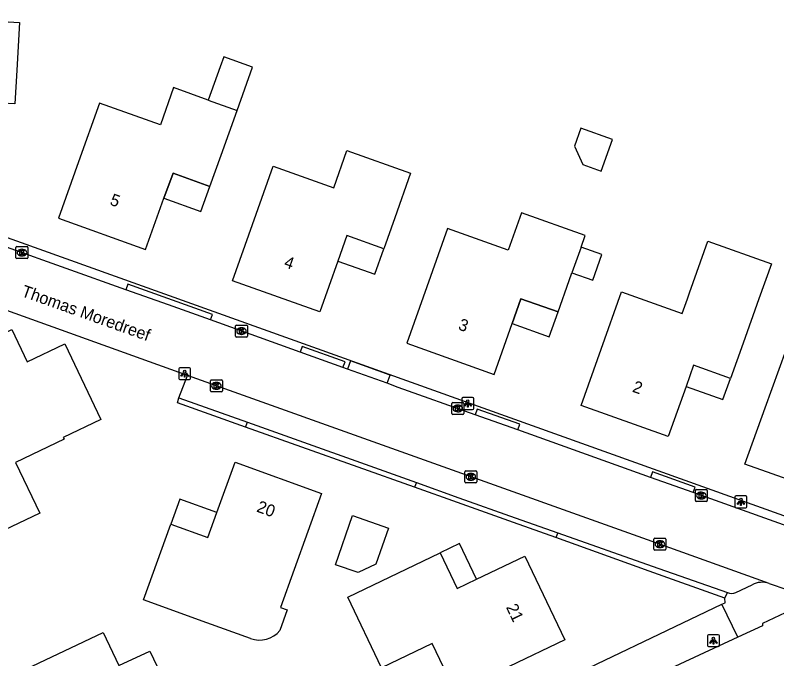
# Model space of a CAD drawing. Extents: x 163268 to 164360, y 381529 to 382285.
# Drawn here: x 163633.8 to 163697.5, y 381632.5 to 381686.4 of the extents above; entities that cross this region are included whole.
import ezdxf

# ---------------------------------------------------------------- set-up
doc = ezdxf.new("R2010")
doc.units = 0
for name, color, linetype in [('IMGEO_Fietspad_gesloten', 7, 'Continuous'), ('IMGEO_Groenvoorziening', 7, 'Continuous'), ('IMGEO_Kolk', 7, 'Continuous'), ('IMGEO_Lichtpunt', 7, 'Continuous'), ('IMGEO_Openbare_ruimte_label', 7, 'Continuous'), ('IMGEO_Pand', 7, 'Continuous'), ('IMGEO_Pand_nummerreeks', 7, 'Continuous'), ('IMGEO_Pand_overbouw', 7, 'Continuous'), ('IMGEO_Parkeervlak_open', 7, 'Continuous'), ('IMGEO_Rijbaan_lokaal_open', 7, 'Continuous'), ('IMGEO_Voetpad_open', 7, 'Continuous')]:
    doc.layers.add(name, color=color, linetype=linetype)

msp = doc.modelspace()

# ---------------------------------------------------------------- linework, layer by layer
at = {"layer": 'IMGEO_Fietspad_gesloten'}
for points in [[(163698.247, 381636.386), (163696.339, 381635.498), (163696.333, 381635.308), (163694.284, 381634.354)], [(163694.284, 381634.354), (163682.934, 381629.066), (163588.96, 381585.345)]]:
    msp.add_lwpolyline(points, dxfattribs=at)
at = {"layer": 'IMGEO_Groenvoorziening'}
for points in [[(163692.948, 381637.102), (163693.217, 381637.23), (163693.201, 381637.598)], [(163623.496, 381604.168), (163677.889, 381629.916), (163692.948, 381637.102)], [(163694.284, 381634.354), (163692.948, 381637.102)]]:
    msp.add_lwpolyline(points, dxfattribs=at)
at = {"layer": 'IMGEO_Kolk'}
for p, q in [((163633.827, 381666.099), (163633.827, 381666.951)), ((163633.902, 381667.025), (163634.754, 381667.025)), ((163634.828, 381666.951), (163634.828, 381666.099)), ((163634.315, 381666.805), (163634.34, 381666.805)), ((163634.754, 381666.025), (163633.902, 381666.025)), ((163634.338, 381666.245), (163634.313, 381666.245)), ((163652.211, 381659.532), (163652.211, 381660.384)), ((163652.286, 381660.458), (163653.138, 381660.458)), ((163652.699, 381660.238), (163652.724, 381660.238)), ((163653.212, 381660.384), (163653.212, 381659.532)), ((163653.138, 381659.458), (163652.286, 381659.458)), ((163652.722, 381659.678), (163652.697, 381659.678)), ((163650.11, 381654.948), (163650.11, 381655.8)), ((163650.185, 381655.874), (163651.037, 381655.874)), ((163650.598, 381655.654), (163650.623, 381655.654)), ((163651.111, 381655.8), (163651.111, 381654.948)), ((163651.037, 381654.874), (163650.185, 381654.874)), ((163650.621, 381655.094), (163650.596, 381655.094)), ((163670.325, 381653.059), (163670.325, 381653.911)), ((163670.4, 381653.985), (163671.252, 381653.985)), ((163670.813, 381653.765), (163670.838, 381653.765)), ((163671.326, 381653.911), (163671.326, 381653.059)), ((163671.252, 381652.985), (163670.4, 381652.985)), ((163670.836, 381653.205), (163670.811, 381653.205)), ((163671.421, 381647.336), (163671.421, 381648.188)), ((163671.496, 381648.262), (163672.348, 381648.262)), ((163671.909, 381648.042), (163671.934, 381648.042)), ((163672.422, 381648.188), (163672.422, 381647.336)), ((163672.348, 381647.262), (163671.496, 381647.262)), ((163671.932, 381647.482), (163671.907, 381647.482)), ((163690.722, 381645.769), (163690.722, 381646.621)), ((163690.797, 381646.695), (163691.649, 381646.695)), ((163691.723, 381646.621), (163691.723, 381645.769)), ((163691.233, 381645.915), (163691.208, 381645.915)), ((163691.21, 381646.475), (163691.235, 381646.475)), ((163691.649, 381645.695), (163690.797, 381645.695)), ((163687.255, 381641.699), (163687.255, 381642.551)), ((163687.33, 381642.625), (163688.182, 381642.625)), ((163687.743, 381642.405), (163687.768, 381642.405)), ((163688.256, 381642.551), (163688.256, 381641.699)), ((163688.182, 381641.625), (163687.33, 381641.625)), ((163687.766, 381641.845), (163687.741, 381641.845))]:
    msp.add_line(p, q, dxfattribs=at)
for points in [[(163633.827, 381666.099), (163633.827, 381666.951)], [(163633.902, 381667.025), (163634.754, 381667.025)], [(163634.828, 381666.951), (163634.828, 381666.099)], [(163634.148, 381666.725), (163634.271, 381666.725), (163634.271, 381666.574), (163634.401, 381666.725), (163634.565, 381666.725), (163634.419, 381666.574), (163634.572, 381666.325), (163634.42, 381666.325), (163634.335, 381666.489), (163634.271, 381666.422), (163634.271, 381666.325), (163634.148, 381666.325), (163634.148, 381666.725)], [(163634.754, 381666.025), (163633.902, 381666.025)], [(163652.211, 381659.532), (163652.211, 381660.384)], [(163652.286, 381660.458), (163653.138, 381660.458)], [(163652.532, 381660.158), (163652.655, 381660.158), (163652.655, 381660.007), (163652.785, 381660.158), (163652.949, 381660.158), (163652.803, 381660.007), (163652.956, 381659.758), (163652.804, 381659.758), (163652.719, 381659.922), (163652.655, 381659.855), (163652.655, 381659.758), (163652.532, 381659.758), (163652.532, 381660.158)], [(163653.212, 381660.384), (163653.212, 381659.532)], [(163653.138, 381659.458), (163652.286, 381659.458)], [(163650.11, 381654.948), (163650.11, 381655.8)], [(163650.185, 381655.874), (163651.037, 381655.874)], [(163650.431, 381655.574), (163650.554, 381655.574), (163650.554, 381655.423), (163650.684, 381655.574), (163650.848, 381655.574), (163650.702, 381655.423), (163650.855, 381655.174), (163650.703, 381655.174), (163650.618, 381655.338), (163650.554, 381655.271), (163650.554, 381655.174), (163650.431, 381655.174), (163650.431, 381655.574)], [(163651.111, 381655.8), (163651.111, 381654.948)], [(163651.037, 381654.874), (163650.185, 381654.874)], [(163670.325, 381653.059), (163670.325, 381653.911)], [(163670.4, 381653.985), (163671.252, 381653.985)], [(163670.646, 381653.685), (163670.769, 381653.685), (163670.769, 381653.534), (163670.899, 381653.685), (163671.063, 381653.685), (163670.917, 381653.534), (163671.07, 381653.285), (163670.918, 381653.285), (163670.833, 381653.449), (163670.769, 381653.382), (163670.769, 381653.285), (163670.646, 381653.285), (163670.646, 381653.685)], [(163671.326, 381653.911), (163671.326, 381653.059)], [(163671.252, 381652.985), (163670.4, 381652.985)], [(163671.421, 381647.336), (163671.421, 381648.188)], [(163671.496, 381648.262), (163672.348, 381648.262)], [(163671.742, 381647.962), (163671.865, 381647.962), (163671.865, 381647.811), (163671.995, 381647.962), (163672.159, 381647.962), (163672.013, 381647.811), (163672.166, 381647.562), (163672.014, 381647.562), (163671.929, 381647.726), (163671.865, 381647.659), (163671.865, 381647.562), (163671.742, 381647.562), (163671.742, 381647.962)], [(163672.422, 381648.188), (163672.422, 381647.336)], [(163672.348, 381647.262), (163671.496, 381647.262)], [(163690.722, 381645.769), (163690.722, 381646.621)], [(163690.797, 381646.695), (163691.649, 381646.695)], [(163691.723, 381646.621), (163691.723, 381645.769)], [(163691.043, 381646.395), (163691.166, 381646.395), (163691.166, 381646.244), (163691.296, 381646.395), (163691.46, 381646.395), (163691.314, 381646.244), (163691.467, 381645.995), (163691.315, 381645.995), (163691.23, 381646.159), (163691.166, 381646.092), (163691.166, 381645.995), (163691.043, 381645.995), (163691.043, 381646.395)], [(163691.649, 381645.695), (163690.797, 381645.695)], [(163687.255, 381641.699), (163687.255, 381642.551)], [(163687.33, 381642.625), (163688.182, 381642.625)], [(163687.576, 381642.325), (163687.699, 381642.325), (163687.699, 381642.174), (163687.829, 381642.325), (163687.993, 381642.325), (163687.847, 381642.174), (163688, 381641.925), (163687.848, 381641.925), (163687.763, 381642.089), (163687.699, 381642.022), (163687.699, 381641.925), (163687.576, 381641.925), (163687.576, 381642.325)], [(163688.256, 381642.551), (163688.256, 381641.699)], [(163688.182, 381641.625), (163687.33, 381641.625)]]:
    msp.add_lwpolyline(points, dxfattribs=at)
for centre, start, end in [((163633.904, 381666.949), 91.55205, 178.44795), ((163633.904, 381666.949), 91.55205, 178.44795), ((163634.752, 381666.949), 1.55205, 88.44795), ((163634.752, 381666.949), 1.55205, 88.44795), ((163633.904, 381666.101), 181.55205, 268.44795), ((163633.904, 381666.101), 181.55205, 268.44795), ((163634.752, 381666.101), 271.55205, 358.44795), ((163634.752, 381666.101), 271.55205, 358.44795), ((163652.288, 381660.382), 91.55205, 178.44795), ((163652.288, 381660.382), 91.55205, 178.44795), ((163653.136, 381660.382), 1.55205, 88.44795), ((163653.136, 381660.382), 1.55205, 88.44795), ((163652.288, 381659.534), 181.55205, 268.44795), ((163652.288, 381659.534), 181.55205, 268.44795), ((163653.136, 381659.534), 271.55205, 358.44795), ((163653.136, 381659.534), 271.55205, 358.44795), ((163650.187, 381655.798), 91.55205, 178.44795), ((163650.187, 381655.798), 91.55205, 178.44795), ((163651.035, 381655.798), 1.55205, 88.44795), ((163651.035, 381655.798), 1.55205, 88.44795), ((163650.187, 381654.95), 181.55205, 268.44795), ((163650.187, 381654.95), 181.55205, 268.44795), ((163651.035, 381654.95), 271.55205, 358.44795), ((163651.035, 381654.95), 271.55205, 358.44795), ((163670.402, 381653.909), 91.55205, 178.44795), ((163670.402, 381653.909), 91.55205, 178.44795), ((163671.25, 381653.909), 1.55205, 88.44795), ((163671.25, 381653.909), 1.55205, 88.44795), ((163670.402, 381653.061), 181.55205, 268.44795), ((163670.402, 381653.061), 181.55205, 268.44795), ((163671.25, 381653.061), 271.55205, 358.44795), ((163671.25, 381653.061), 271.55205, 358.44795), ((163671.498, 381648.186), 91.55205, 178.44795), ((163671.498, 381648.186), 91.55205, 178.44795), ((163672.346, 381648.186), 1.55205, 88.44795), ((163672.346, 381648.186), 1.55205, 88.44795), ((163671.498, 381647.338), 181.55205, 268.44795), ((163671.498, 381647.338), 181.55205, 268.44795), ((163672.346, 381647.338), 271.55205, 358.44795), ((163672.346, 381647.338), 271.55205, 358.44795), ((163690.799, 381646.619), 91.55205, 178.44795), ((163690.799, 381646.619), 91.55205, 178.44795), ((163691.647, 381646.619), 1.55205, 88.44795), ((163691.647, 381646.619), 1.55205, 88.44795), ((163690.799, 381645.771), 181.55205, 268.44795), ((163690.799, 381645.771), 181.55205, 268.44795), ((163691.647, 381645.771), 271.55205, 358.44795), ((163691.647, 381645.771), 271.55205, 358.44795), ((163687.332, 381642.549), 91.55205, 178.44795), ((163687.332, 381642.549), 91.55205, 178.44795), ((163688.18, 381642.549), 1.55205, 88.44795), ((163688.18, 381642.549), 1.55205, 88.44795), ((163687.332, 381641.701), 181.55205, 268.44795), ((163687.332, 381641.701), 181.55205, 268.44795), ((163688.18, 381641.701), 271.55205, 358.44795), ((163688.18, 381641.701), 271.55205, 358.44795)]:
    msp.add_arc(centre, 0.0765, start, end, dxfattribs=at)
for centre, major_axis, ratio, start_param, end_param in [((163634.314, 381666.525), (-0.387, 0.002), 0.722429, 4.712389, 7.853982), ((163634.339, 381666.525), (-0.39, 0.002), 0.717154, 1.570796, 4.712389), ((163652.698, 381659.958), (-0.387, 0.002), 0.722429, 4.712389, 7.853982), ((163652.723, 381659.958), (-0.39, 0.002), 0.717154, 1.570796, 4.712389), ((163650.597, 381655.374), (-0.387, 0.002), 0.722429, 4.712389, 7.853982), ((163650.622, 381655.374), (-0.39, 0.002), 0.717154, 1.570796, 4.712389), ((163670.812, 381653.485), (-0.387, 0.002), 0.722429, 4.712389, 7.853982), ((163670.837, 381653.485), (-0.39, 0.002), 0.717154, 1.570796, 4.712389), ((163671.908, 381647.762), (-0.387, 0.002), 0.722429, 4.712389, 7.853982), ((163671.933, 381647.762), (-0.39, 0.002), 0.717154, 1.570796, 4.712389), ((163691.209, 381646.195), (-0.387, 0.002), 0.722429, 4.712389, 7.853982), ((163691.234, 381646.195), (-0.39, 0.002), 0.717154, 1.570796, 4.712389), ((163687.742, 381642.125), (-0.387, 0.002), 0.722429, 4.712389, 7.853982), ((163687.767, 381642.125), (-0.39, 0.002), 0.717154, 1.570796, 4.712389)]:
    msp.add_ellipse(centre, major_axis=major_axis, ratio=ratio, start_param=start_param, end_param=end_param, dxfattribs=at)
at = {"layer": 'IMGEO_Lichtpunt'}
for p, q in [((163647.455, 381656.797), (163647.455, 381655.99)), ((163647.455, 381656.797), (163647.455, 381655.99)), ((163648.357, 381656.892), (163647.549, 381656.892)), ((163648.357, 381656.892), (163647.549, 381656.892)), ((163648.451, 381655.99), (163648.451, 381656.797)), ((163648.451, 381655.99), (163648.451, 381656.797)), ((163647.549, 381655.896), (163648.357, 381655.896)), ((163647.549, 381655.896), (163648.357, 381655.896)), ((163671.162, 381654.297), (163671.162, 381653.49)), ((163671.162, 381654.297), (163671.162, 381653.49)), ((163672.064, 381654.392), (163671.256, 381654.392)), ((163672.064, 381654.392), (163671.256, 381654.392)), ((163672.158, 381653.49), (163672.158, 381654.297)), ((163672.158, 381653.49), (163672.158, 381654.297)), ((163671.256, 381653.396), (163672.064, 381653.396)), ((163671.256, 381653.396), (163672.064, 381653.396)), ((163694.039, 381646.073), (163694.039, 381645.266)), ((163694.039, 381646.073), (163694.039, 381645.266)), ((163694.941, 381646.168), (163694.133, 381646.168)), ((163694.941, 381646.168), (163694.133, 381646.168)), ((163695.035, 381645.266), (163695.035, 381646.073)), ((163695.035, 381645.266), (163695.035, 381646.073)), ((163694.133, 381645.172), (163694.941, 381645.172)), ((163694.133, 381645.172), (163694.941, 381645.172)), ((163691.738, 381634.455), (163691.738, 381633.648)), ((163691.738, 381634.455), (163691.738, 381633.648)), ((163692.64, 381634.55), (163691.832, 381634.55)), ((163692.64, 381634.55), (163691.832, 381634.55)), ((163692.734, 381633.648), (163692.734, 381634.455)), ((163692.734, 381633.648), (163692.734, 381634.455)), ((163691.832, 381633.554), (163692.64, 381633.554)), ((163691.832, 381633.554), (163692.64, 381633.554))]:
    msp.add_line(p, q, dxfattribs=at)
for points in [[(163647.829, 381656.461), (163647.868, 381656.433), (163647.68, 381656.171), (163647.642, 381656.198), (163647.829, 381656.461)], [(163647.931, 381656.413), (163647.978, 381656.413), (163647.978, 381656.091), (163647.931, 381656.091), (163647.931, 381656.413)], [(163648.041, 381656.433), (163648.079, 381656.46), (163648.266, 381656.198), (163648.227, 381656.17), (163648.041, 381656.433)], [(163671.536, 381653.961), (163671.575, 381653.933), (163671.387, 381653.671), (163671.349, 381653.698), (163671.536, 381653.961)], [(163671.638, 381653.913), (163671.685, 381653.913), (163671.685, 381653.591), (163671.638, 381653.591), (163671.638, 381653.913)], [(163671.748, 381653.933), (163671.786, 381653.96), (163671.973, 381653.698), (163671.934, 381653.67), (163671.748, 381653.933)], [(163694.413, 381645.737), (163694.452, 381645.709), (163694.264, 381645.447), (163694.226, 381645.474), (163694.413, 381645.737)], [(163694.515, 381645.689), (163694.562, 381645.689), (163694.562, 381645.367), (163694.515, 381645.367), (163694.515, 381645.689)], [(163694.625, 381645.709), (163694.663, 381645.736), (163694.85, 381645.474), (163694.811, 381645.446), (163694.625, 381645.709)], [(163692.112, 381634.119), (163692.151, 381634.091), (163691.963, 381633.829), (163691.925, 381633.856), (163692.112, 381634.119)], [(163692.214, 381634.071), (163692.261, 381634.071), (163692.261, 381633.749), (163692.214, 381633.749), (163692.214, 381634.071)], [(163692.324, 381634.091), (163692.362, 381634.118), (163692.549, 381633.856), (163692.51, 381633.828), (163692.324, 381634.091)]]:
    msp.add_lwpolyline(points, dxfattribs=at)
for centre in [(163647.954, 381656.595), (163671.661, 381654.095), (163694.538, 381645.871), (163692.237, 381634.253)]:
    msp.add_circle(centre, 0.0994, dxfattribs=at)
for centre, start, end in [((163647.549, 381656.797), 90, 180), ((163647.549, 381656.797), 90, 180), ((163648.357, 381656.797), 0, 90), ((163648.357, 381656.797), 0, 90), ((163647.549, 381655.99), 180, 270), ((163647.549, 381655.99), 180, 270), ((163648.357, 381655.99), 270, 0), ((163648.357, 381655.99), 270, 360), ((163671.256, 381654.297), 90, 180), ((163671.256, 381654.297), 90, 180), ((163672.064, 381654.297), 0, 90), ((163672.064, 381654.297), 0, 90), ((163671.256, 381653.49), 180, 270), ((163671.256, 381653.49), 180, 270), ((163672.064, 381653.49), 270, 0), ((163672.064, 381653.49), 270, 360), ((163694.133, 381646.073), 90, 180), ((163694.133, 381646.073), 90, 180), ((163694.941, 381646.073), 0, 90), ((163694.941, 381646.073), 0, 90), ((163694.133, 381645.266), 180, 270), ((163694.133, 381645.266), 180, 270), ((163694.941, 381645.266), 270, 0), ((163694.941, 381645.266), 270, 360), ((163691.832, 381634.455), 90, 180), ((163691.832, 381634.455), 90, 180), ((163692.64, 381634.455), 0, 90), ((163692.64, 381634.455), 0, 90), ((163691.832, 381633.648), 180, 270), ((163691.832, 381633.648), 180, 270), ((163692.64, 381633.648), 270, 0), ((163692.64, 381633.648), 270, 360)]:
    msp.add_arc(centre, 0.0946, start, end, dxfattribs=at)
at = {"layer": 'IMGEO_Pand'}
for points in [[(163630.045, 381672.483), (163622.26, 381672.933), (163622.545, 381677.925), (163622.841, 381683.109), (163623.419, 381683.076), (163623.607, 381686.383), (163628.458, 381686.107), (163634.117, 381685.785), (163633.89, 381681.792), (163633.729, 381678.958), (163630.424, 381679.148), (163630.301, 381676.99), (163630.045, 381672.483)], [(163652.35, 381678.42), (163653.64, 381682.051), (163651.228, 381682.917), (163650.92, 381682.056), (163649.928, 381679.289)], [(163649.928, 381679.289), (163647.03, 381680.33), (163645.92, 381677.22), (163640.82, 381679.04), (163639.061, 381674.116), (163637.378, 381669.407), (163644.664, 381666.775), (163646.22, 381671.07), (163646.979, 381673.165), (163650.071, 381672.058), (163651.006, 381674.668), (163652.35, 381678.42)], [(163649.928, 381679.289), (163652.35, 381678.42)], [(163680.597, 381675.432), (163681.295, 381673.886), (163682.838, 381673.337), (163683.783, 381675.995), (163681.133, 381676.937), (163680.597, 381675.432)], [(163660.437, 381671.946), (163661.539, 381675.054), (163666.879, 381673.163), (163665.554, 381669.421), (163664.643, 381666.85), (163661.536, 381667.951), (163660.777, 381665.808), (163659.277, 381661.572), (163651.959, 381664.169), (163653.629, 381668.882), (163655.352, 381673.746), (163660.437, 381671.946)], [(163681.151, 381666.989), (163681.492, 381667.948), (163676.156, 381669.845), (163675.049, 381666.733), (163669.958, 381668.542), (163668.224, 381663.666), (163666.549, 381658.954), (163673.862, 381656.338), (163675.37, 381660.58), (163676.118, 381662.664), (163679.224, 381661.565), (163680.155, 381664.185), (163680.387, 381664.839)], [(163681.151, 381666.989), (163680.387, 381664.839)], [(163680.387, 381664.839), (163682.137, 381664.217), (163682.901, 381666.367), (163681.151, 381666.989)], [(163689.617, 381661.442), (163690.051, 381662.657), (163690.228, 381663.153), (163691.776, 381667.484), (163697.089, 381665.587), (163696.039, 381662.646), (163694.713, 381658.933), (163693.663, 381655.994), (163690.571, 381657.099), (163689.939, 381655.329), (163688.444, 381651.141), (163681.146, 381653.732), (163682.828, 381658.441), (163684.547, 381663.252), (163689.617, 381661.442)], [(163696.58, 381653.535), (163698.334, 381658.38), (163702.582, 381656.843), (163704.185, 381661.269), (163710.349, 381659.037), (163708.52, 381653.986), (163707.51, 381651.196), (163704.411, 381652.319), (163703.718, 381650.408), (163702.208, 381646.242), (163694.877, 381648.833), (163696.58, 381653.535)], [(163635.811, 381644.72), (163629.88, 381641.895), (163626.086, 381649.857), (163629.066, 381651.277), (163628.4, 381652.675), (163626.469, 381656.729), (163633.483, 381660.082), (163634.774, 381657.374), (163637.931, 381658.883), (163640.943, 381652.564), (163637.785, 381651.055), (163637.858, 381650.901), (163633.788, 381648.962), (163635.811, 381644.72)], [(163653.457, 381634.224), (163649.802, 381635.545), (163644.505, 381637.46), (163646.801, 381643.81), (163649.903, 381642.688), (163650.654, 381644.765), (163652.179, 381648.983), (163659.425, 381646.357)], [(163659.425, 381646.357), (163655.981, 381636.832), (163656.55, 381636.626), (163655.931, 381634.914)], [(163660.58, 381640.404), (163662.013, 381644.518), (163665.013, 381643.473), (163663.961, 381640.454), (163662.475, 381639.744), (163660.58, 381640.404)], [(163676.437, 381641.129), (163679.784, 381634.13), (163675.133, 381631.906), (163675.564, 381631.004), (163671.956, 381629.278), (163671.524, 381630.18), (163670.622, 381629.749), (163668.676, 381633.817), (163664.435, 381631.789), (163661.609, 381637.698), (163669.356, 381641.402), (163670.779, 381638.424), (163672.396, 381639.197), (163676.437, 381641.129)], [(163642.451, 381631.971), (163645.039, 381633.188), (163649.24, 381624.353), (163647.508, 381623.539), (163646.25, 381623.982), (163645.49, 381625.58), (163640.6, 381623.28), (163642.01, 381620.29), (163636.903, 381617.844), (163633.799, 381624.303), (163636.83, 381625.741), (163636.05, 381627.37), (163634.12, 381631.42), (163641.13, 381634.75), (163642.451, 381631.971)]]:
    msp.add_lwpolyline(points, dxfattribs=at)
msp.add_arc((163654.182, 381636.403), 2.297, 251.58719, 319.58044, dxfattribs=at)
at = {"layer": 'IMGEO_Pand_overbouw'}
for points in [[(163650.071, 381672.058), (163646.979, 381673.165), (163646.22, 381671.07), (163649.32, 381669.96)], [(163664.643, 381666.85), (163661.536, 381667.951), (163660.777, 381665.808), (163663.884, 381664.707)], [(163679.224, 381661.565), (163676.118, 381662.664), (163675.37, 381660.58), (163678.48, 381659.473)], [(163693.663, 381655.994), (163690.571, 381657.099), (163689.939, 381655.329), (163693.031, 381654.224)], [(163650.654, 381644.765), (163647.552, 381645.887), (163646.801, 381643.81), (163649.903, 381642.688)], [(163670.973, 381642.175), (163669.356, 381641.402), (163670.779, 381638.424), (163672.396, 381639.197)]]:
    msp.add_lwpolyline(points, close=True, dxfattribs=at)
at = {"layer": 'IMGEO_Parkeervlak_open'}
for points in [[(163647.464, 381654.37), (163648.186, 381656.239)], [(163694.114, 381638.096), (163695.472, 381638.725)]]:
    msp.add_lwpolyline(points, dxfattribs=at)
for centre, radius, start, end in [((163696.334, 381637.121), 1.821, 71.72512, 118.24542), ((163693.743, 381638.813), 0.808, 245.57674, 297.34836)]:
    msp.add_arc(centre, radius, start, end, dxfattribs=at)
at = {"layer": 'IMGEO_Rijbaan_lokaal_open'}
for points in [[(163643.027, 381663.418), (163633.033, 381666.99)], [(163650.107, 381660.888), (163646.599, 381662.142), (163643.027, 381663.418)], [(163648.186, 381656.239), (163629.853, 381662.817)], [(163657.637, 381658.197), (163650.107, 381660.888)], [(163661.21, 381656.897), (163657.637, 381658.197)], [(163661.583, 381656.764), (163661.21, 381656.897)], [(163664.921, 381655.593), (163661.583, 381656.764)], [(163696.905, 381638.85), (163687.483, 381642.223), (163648.186, 381656.239)], [(163672.283, 381652.963), (163665.837, 381655.241), (163664.921, 381655.593)], [(163675.841, 381651.691), (163672.283, 381652.963)], [(163686.952, 381647.72), (163675.841, 381651.691)], [(163690.54, 381646.438), (163686.952, 381647.72)], [(163701.053, 381642.681), (163690.54, 381646.438)], [(163696.905, 381638.85), (163698.391, 381638.347)]]:
    msp.add_lwpolyline(points, dxfattribs=at)
at = {"layer": 'IMGEO_Voetpad_open'}
for points in [[(163629.716, 381668.998), (163704.116, 381642.385)], [(163650.107, 381660.888), (163650.275, 381661.358), (163643.195, 381663.888), (163643.027, 381663.418)], [(163661.21, 381656.897), (163661.385, 381657.388), (163657.805, 381658.667), (163657.637, 381658.197)], [(163664.921, 381655.593), (163665.162, 381656.282), (163661.829, 381657.472), (163661.583, 381656.764)], [(163653.06, 381651.93), (163647.357, 381653.958), (163647.464, 381654.37)], [(163647.464, 381654.37), (163653.209, 381652.324)], [(163675.841, 381651.691), (163676.009, 381652.161), (163672.451, 381653.433), (163672.283, 381652.963)], [(163653.06, 381651.93), (163653.209, 381652.324)], [(163653.209, 381652.324), (163667.36, 381647.283)], [(163667.214, 381646.884), (163653.06, 381651.93)], [(163690.54, 381646.438), (163690.708, 381646.908), (163687.12, 381648.19), (163686.952, 381647.72)], [(163667.36, 381647.283), (163667.214, 381646.884)], [(163667.36, 381647.283), (163670.924, 381646.013), (163675.637, 381644.335), (163679.195, 381643.067)], [(163679.05, 381642.678), (163675.489, 381643.937), (163670.794, 381645.621), (163667.214, 381646.884)], [(163679.195, 381643.067), (163679.05, 381642.678)], [(163693.201, 381637.598), (163686.863, 381639.858), (163679.05, 381642.678)], [(163679.195, 381643.067), (163687.117, 381640.288), (163693.409, 381638.078)], [(163693.201, 381637.598), (163693.409, 381638.078)]]:
    msp.add_lwpolyline(points, dxfattribs=at)

# ---------------------------------------------------------------- texts
at = {"layer": 'IMGEO_Openbare_ruimte_label'}
msp.add_text('Thomas Moredreef', height=1, rotation=340.3693, dxfattribs=at).set_placement((163634.209, 381662.898))
at = {"layer": 'IMGEO_Pand_nummerreeks'}
for s, rotation, p in [('5', 340.13555, (163641.618, 381670.554)), ('4', 340.46214, (163656.202, 381665.338)), ('3', 340.3189, (163670.795, 381660.111)), ('2', 340.45641, (163685.377, 381654.903)), ('20', 340.07826, (163653.91, 381644.868)), ('21', 295.55944, (163674.843, 381636.857))]:
    msp.add_text(s, height=1, rotation=rotation, dxfattribs=at).set_placement(p)

doc.saveas('drawing.dxf')
